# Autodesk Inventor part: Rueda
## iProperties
Created: 2008-01
Part Number: Rueda
Document SubType Name: Modeling
Designer: eruiz-tagle
Mass: 1.2797 g
Surface Area: 24.0293 cm^2
Volume: 1.2797 cm^3
Density: 1 g/cm^3
Author: eruiz-tagle
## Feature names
1. Revolution1
2. Shell1
3. Revolution2
4. Circular Pattern1
